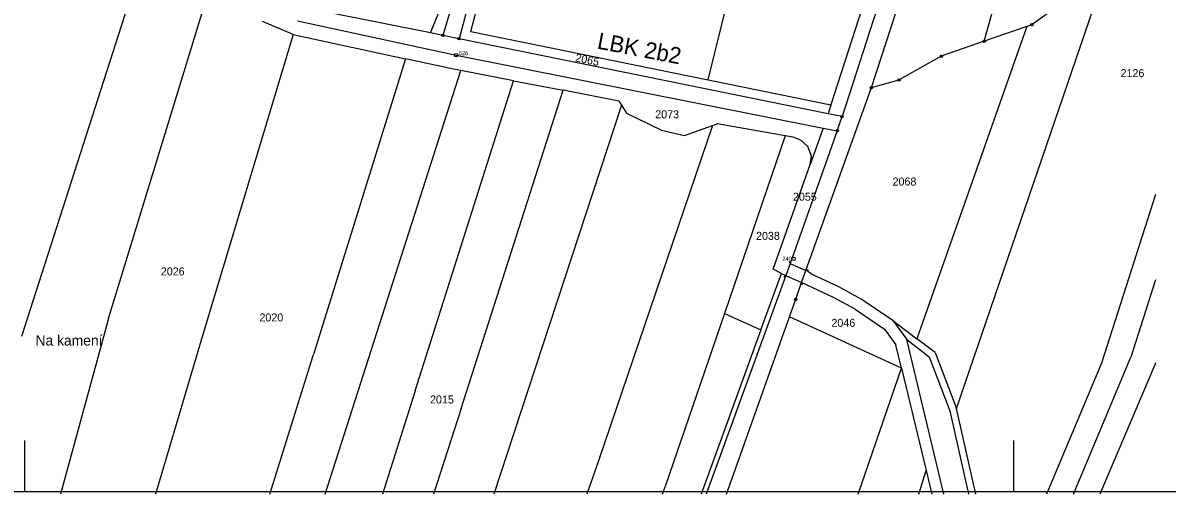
# Model space of a CAD drawing. Extents: x -566461 to -565197, y -1096302 to -1095706.
# Drawn here: x -566039.2 to -565553.3, y -1096301.9 to -1096101.6 of the extents above; entities that cross this region are included whole.
import ezdxf

# ---------------------------------------------------------------- set-up
doc = ezdxf.new("R2010")
doc.units = 0
for name, color, linetype in [('Vrstva 1', 7, 'Continuous'), ('Vrstva 15', 7, 'Continuous'), ('Vrstva 17', 7, 'Continuous'), ('Vrstva 18', 7, 'Continuous'), ('Vrstva 24', 7, 'Continuous'), ('Vrstva 26', 7, 'Continuous'), ('Vrstva 4', 7, 'Continuous'), ('Vrstva 63', 7, 'Continuous')]:
    doc.layers.add(name, color=color, linetype=linetype)

msp = doc.modelspace()

# ---------------------------------------------------------------- linework, layer by layer
at = {"layer": 'Vrstva 1'}
for p, q in [((-565836.72, -1096024.67), (-565860.88, -1096106.94)), ((-565832.07, -1096026.09), (-565854, -1096108.33)), ((-565655.73, -1096030.58), (-565691.34, -1096141.44)), ((-565678.86, -1096129.12), (-565647.61, -1096033.2)), ((-565663.31, -1096034.56), (-565696.05, -1096136.4)), ((-565630.9, -1096109.42), (-565610.93, -1096037.81)), ((-565849.04, -1096105.26), (-565838.03, -1096063.98)), ((-566039.72, -1096234.72), (-565988.25, -1096074.11)), ((-566002.86, -1096227.33), (-565957.4, -1096078.54)), ((-565748.22, -1096125.78), (-565736.97, -1096079.98)), ((-565866.09, -1096105.89), (-565860.59, -1096092.38)), ((-565642.73, -1096265.59), (-565584.54, -1096095.4)), ((-565598.72, -1096093.8), (-565610.72, -1096102.41)), ((-565924.47, -1096106.51), (-565937.44, -1096101.01)), ((-565922.65, -1096100.77), (-565855.22, -1096115.35)), ((-565866.09, -1096105.89), (-565909.52, -1096097.15)), ((-565860.88, -1096106.94), (-565866.09, -1096105.89)), ((-565849.04, -1096105.26), (-565748.22, -1096125.78)), ((-565612.82, -1096103.14), (-565659.51, -1096235.93)), ((-565612.82, -1096103.14), (-565630.9, -1096109.42)), ((-565610.72, -1096102.41), (-565612.82, -1096103.14)), ((-565924.47, -1096106.51), (-565963.09, -1096235.11)), ((-565924.47, -1096106.51), (-565876.67, -1096116.85)), ((-565854, -1096108.33), (-565860.88, -1096106.94)), ((-565697.28, -1096140.23), (-565854, -1096108.33)), ((-565630.9, -1096109.42), (-565649.17, -1096115.77)), ((-565855.22, -1096115.35), (-565699.29, -1096146.31)), ((-565649.17, -1096115.77), (-565667.09, -1096125.86)), ((-565876.67, -1096116.85), (-565915.86, -1096242.54)), ((-565856.42, -1096121.23), (-565876.67, -1096116.85)), ((-565894.7, -1096251.46), (-565853.27, -1096121.84)), ((-565853.27, -1096121.84), (-565856.42, -1096121.23)), ((-565830.85, -1096126.18), (-565853.27, -1096121.84)), ((-565748.22, -1096125.78), (-565696.05, -1096136.4)), ((-565872.6, -1096257.97), (-565830.85, -1096126.18)), ((-565853.1, -1096265.52), (-565809.72, -1096130.27)), ((-565830.85, -1096126.18), (-565809.72, -1096130.27)), ((-565786.12, -1096134.84), (-565809.72, -1096130.27)), ((-565706.66, -1096206.91), (-565678.86, -1096129.12)), ((-565678.86, -1096129.12), (-565667.09, -1096125.86)), ((-565786.12, -1096134.84), (-565785.01, -1096136.58)), ((-565785.01, -1096136.58), (-565830.71, -1096276)), ((-565785.01, -1096136.58), (-565782.85, -1096139.97)), ((-565782.85, -1096139.97), (-565767.95, -1096147.28)), ((-565696.05, -1096136.4), (-565697.28, -1096140.23)), ((-565691.34, -1096141.44), (-565697.28, -1096140.23)), ((-565746.3, -1096145.21), (-565794.69, -1096287.35)), ((-565758.23, -1096149.51), (-565746.3, -1096145.21)), ((-565746.3, -1096145.21), (-565744.3, -1096144.49)), ((-565715.49, -1096149.63), (-565744.3, -1096144.49)), ((-565693.35, -1096147.49), (-565691.34, -1096141.44)), ((-565767.95, -1096147.28), (-565758.23, -1096149.51)), ((-565715.49, -1096149.63), (-565741.31, -1096225.16)), ((-565712.13, -1096150.23), (-565715.49, -1096149.63)), ((-565693.35, -1096147.49), (-565713.41, -1096203.88)), ((-565699.29, -1096146.31), (-565704.82, -1096161.83)), ((-565699.29, -1096146.31), (-565693.35, -1096147.49)), ((-565708.87, -1096151.41), (-565712.13, -1096150.23)), ((-565705.85, -1096154.11), (-565708.87, -1096151.41)), ((-565704.29, -1096158.29), (-565705.85, -1096154.11)), ((-565704.82, -1096161.83), (-565704.29, -1096158.29)), ((-565720.65, -1096206.33), (-565704.82, -1096161.83)), ((-565558.22, -1096174.62), (-565581.08, -1096246.31)), ((-565725.77, -1096232.1), (-565717.05, -1096208.12)), ((-565717.05, -1096208.12), (-565720.65, -1096206.33)), ((-565717.05, -1096208.12), (-565715.24, -1096209.02)), ((-565713.41, -1096203.88), (-565715.24, -1096209.02)), ((-565708.49, -1096212.04), (-565706.66, -1096206.91)), ((-565706.19, -1096207.05), (-565706.66, -1096206.91)), ((-565704.33, -1096208.45), (-565706.19, -1096207.05)), ((-565692.71, -1096213.82), (-565704.33, -1096208.45)), ((-565715.24, -1096209.02), (-565749.04, -1096301.95)), ((-565711.02, -1096219.1), (-565708.49, -1096212.04)), ((-565694.97, -1096218.28), (-565708.49, -1096212.04)), ((-565558.22, -1096210.86), (-565568.61, -1096243.67)), ((-565683.18, -1096219.08), (-565692.71, -1096213.82)), ((-565713.68, -1096226.59), (-565711.02, -1096219.1)), ((-565685.8, -1096223.34), (-565694.97, -1096218.28)), ((-565669.8, -1096228.19), (-565683.18, -1096219.08)), ((-566002.86, -1096227.33), (-566023.32, -1096301.95)), ((-565741.31, -1096225.16), (-565766.45, -1096298.7)), ((-565741.31, -1096225.16), (-565725.77, -1096232.1)), ((-565740.45, -1096301.95), (-565713.68, -1096226.59)), ((-565666.06, -1096248.46), (-565713.68, -1096226.59)), ((-565685.8, -1096223.34), (-565673.31, -1096231.85)), ((-565725.77, -1096232.1), (-565751.17, -1096301.95)), ((-565673.31, -1096231.85), (-565668.46, -1096238.41)), ((-565669.8, -1096228.19), (-565659.51, -1096235.93)), ((-565669.8, -1096228.19), (-565663.83, -1096236.26)), ((-565963.09, -1096235.11), (-565982.97, -1096301.95)), ((-565663.83, -1096236.26), (-565654.34, -1096243.56)), ((-565648.15, -1096301.95), (-565663.83, -1096236.26)), ((-565651.84, -1096241.7), (-565659.51, -1096235.93)), ((-565666.06, -1096248.46), (-565668.46, -1096238.41)), ((-565651.84, -1096241.7), (-565642.73, -1096265.59)), ((-565934.39, -1096301.95), (-565915.86, -1096242.54)), ((-565654.34, -1096243.56), (-565645.58, -1096266.6)), ((-565581.08, -1096246.31), (-565604.54, -1096301.95)), ((-565593.08, -1096301.95), (-565568.61, -1096243.67)), ((-565558.48, -1096247.01), (-565581.8, -1096301.95)), ((-565558.22, -1096246.19), (-565558.48, -1096247.01)), ((-565910.83, -1096301.95), (-565894.7, -1096251.46)), ((-565684.46, -1096301.95), (-565666.06, -1096248.46)), ((-565666.06, -1096248.46), (-565655.65, -1096291.87)), ((-565872.6, -1096257.97), (-565886.53, -1096301.95)), ((-565853.1, -1096265.52), (-565864.78, -1096301.95)), ((-565645.58, -1096266.6), (-565637.62, -1096301.95)), ((-565634.54, -1096301.95), (-565642.73, -1096265.59)), ((-565830.71, -1096276), (-565839.22, -1096301.95)), ((-565794.69, -1096287.35), (-565799.66, -1096301.95)), ((-565658.72, -1096301.95), (-565655.65, -1096291.87)), ((-565655.65, -1096291.87), (-565653.25, -1096301.95)), ((-565767.56, -1096301.95), (-565766.45, -1096298.7))]:
    msp.add_line(p, q, dxfattribs=at)
at = {"layer": 'Vrstva 24'}
for centre, radius in [((-565610.72, -1096102.41), 0.5), ((-565610.72, -1096102.41), 0.0327), ((-565860.88, -1096106.94), 0.5), ((-565860.88, -1096106.94), 0.0327), ((-565854, -1096108.33), 0.5), ((-565854, -1096108.33), 0.0327), ((-565630.9, -1096109.42), 0.5), ((-565630.9, -1096109.42), 0.0327), ((-565855.22, -1096115.35), 0.75), ((-565855.22, -1096115.35), 0.0327), ((-565649.17, -1096115.77), 0.5), ((-565649.17, -1096115.77), 0.0327), ((-565667.09, -1096125.86), 0.5), ((-565667.09, -1096125.86), 0.0327), ((-565678.86, -1096129.12), 0.5), ((-565678.86, -1096129.12), 0.0327), ((-565691.34, -1096141.44), 0.5), ((-565691.34, -1096141.44), 0.0327), ((-565693.35, -1096147.49), 0.5), ((-565693.35, -1096147.49), 0.0327), ((-565711.93, -1096201.89), 0.75), ((-565711.93, -1096201.89), 0.0327), ((-565711.02, -1096219.1), 0.5), ((-565711.02, -1096219.1), 0.0327)]:
    msp.add_circle(centre, radius, dxfattribs=at)
at = {"layer": 'Vrstva 26'}
for p, q in [((-565713.81, -1096202.97), (-565713.41, -1096203.88)), ((-565705.7, -1096206.62), (-565706.66, -1096206.91)), ((-565716.11, -1096209.51), (-565715.24, -1096209.02)), ((-565708.18, -1096212.99), (-565708.49, -1096212.04))]:
    msp.add_line(p, q, dxfattribs=at)
at = {"layer": 'Vrstva 4'}
for p, q in [((-565713.41, -1096203.88), (-565706.66, -1096206.91)), ((-565715.24, -1096209.02), (-565708.49, -1096212.04))]:
    msp.add_line(p, q, dxfattribs=at)
at = {"layer": 'Vrstva 63'}
for p, q in [((-566038.38, -1096301.03), (-566038.38, -1096279.18)), ((-565618.38, -1096301.03), (-565618.38, -1096279.18)), ((-565198.38, -1096301.03), (-566458.38, -1096301.03))]:
    msp.add_line(p, q, dxfattribs=at)

# ---------------------------------------------------------------- texts
at = {"layer": 'Vrstva 1'}
msp.add_text('LBK 2b2', height=7, rotation=349.0833, dxfattribs=at).set_placement((-565795.66, -1096112.47))
at = {"layer": 'Vrstva 15'}
msp.add_text('Na kamení', height=4.4, dxfattribs=at).set_placement((-566033.89, -1096238.78))
at = {"layer": 'Vrstva 17'}
for s, p in [('526', (-565854.03, -1096115.34)), ('240', (-565716.65, -1096202.74))]:
    msp.add_text(s, height=1.7, dxfattribs=at).set_placement(p)
at = {"layer": 'Vrstva 18'}
msp.add_text('2065', height=3.4, rotation=348.3, dxfattribs=at).set_placement((-565804.83, -1096117.93))
for s, p in [('2126', (-565573.04, -1096124.67)), ('2073', (-565770.68, -1096142.16)), ('2068', (-565669.87, -1096170.75)), ('2055', (-565712.19, -1096177.19)), ('2038', (-565727.86, -1096193.84)), ('2026', (-565980.66, -1096208.96)), ('2020', (-565938.78, -1096228.53)), ('2046', (-565695.84, -1096230.82)), ('2015', (-565866.33, -1096263.41))]:
    msp.add_text(s, height=3.4, dxfattribs=at).set_placement(p)

doc.saveas('drawing.dxf')
